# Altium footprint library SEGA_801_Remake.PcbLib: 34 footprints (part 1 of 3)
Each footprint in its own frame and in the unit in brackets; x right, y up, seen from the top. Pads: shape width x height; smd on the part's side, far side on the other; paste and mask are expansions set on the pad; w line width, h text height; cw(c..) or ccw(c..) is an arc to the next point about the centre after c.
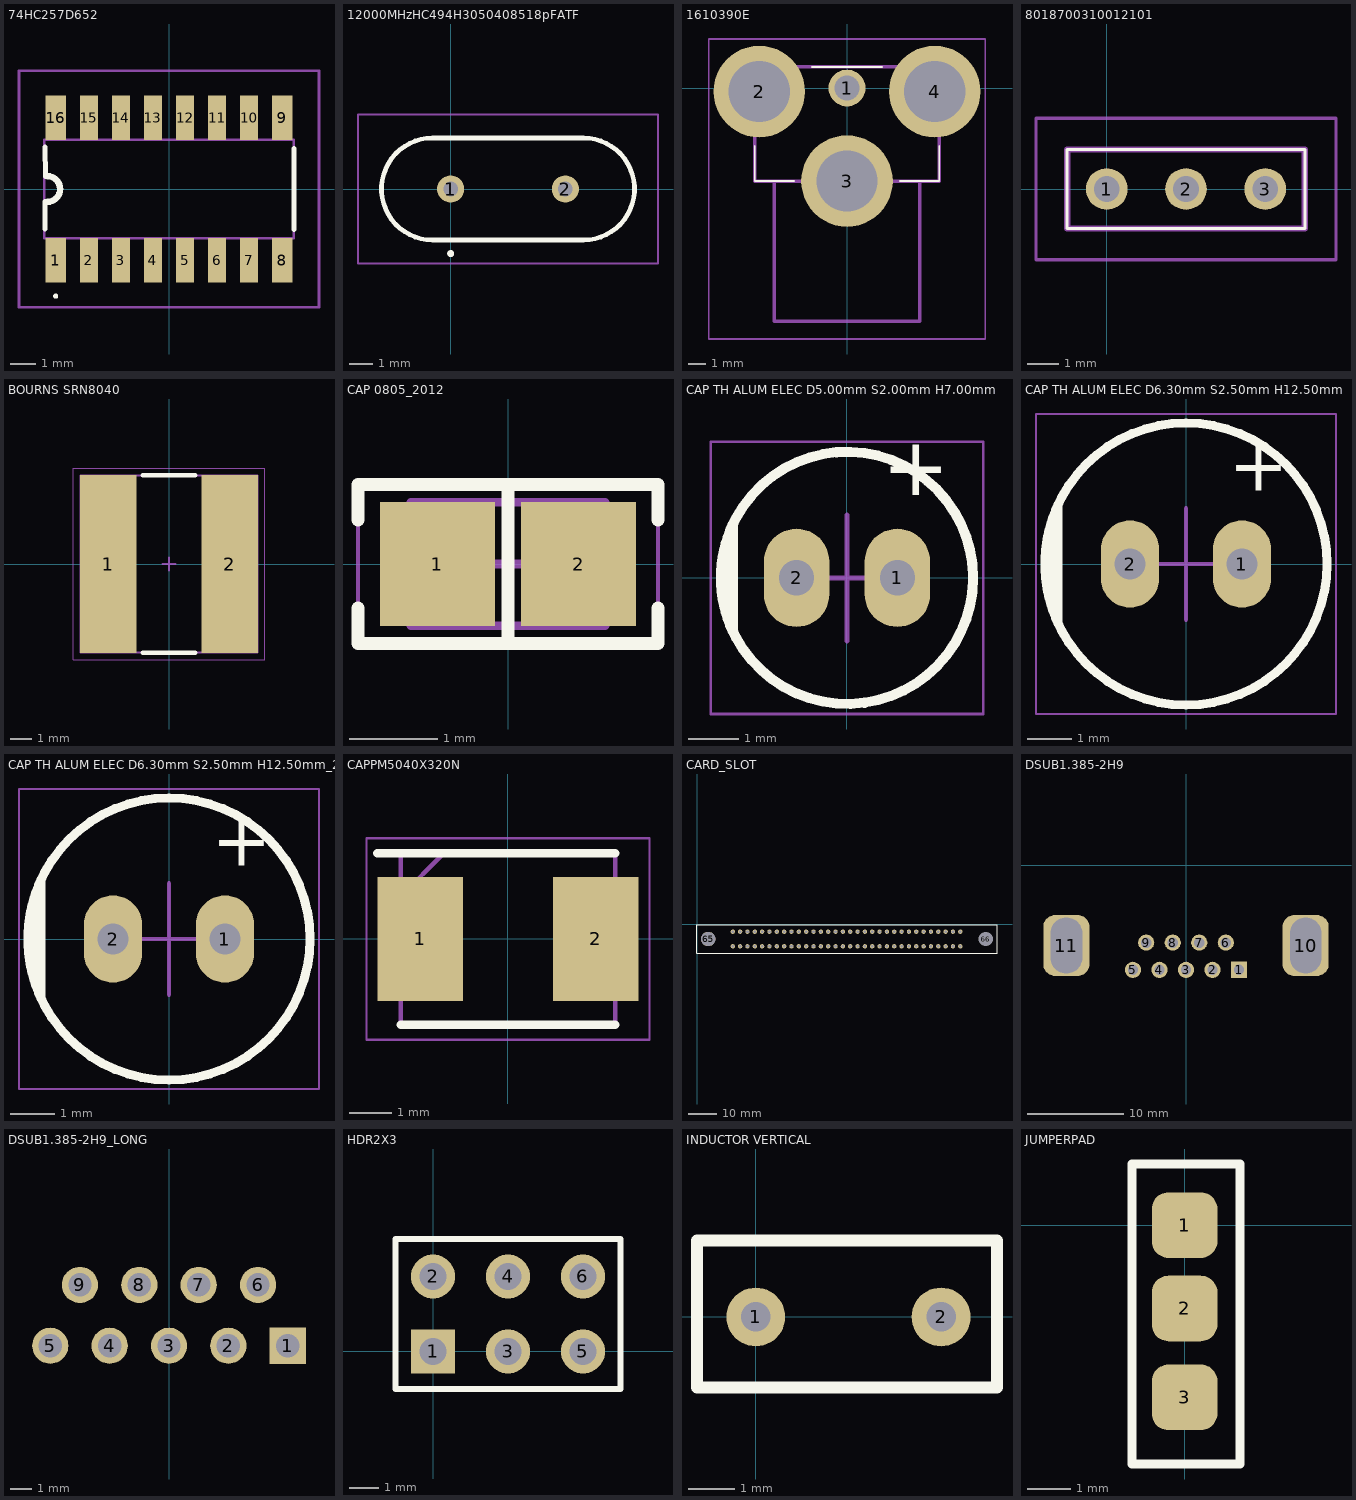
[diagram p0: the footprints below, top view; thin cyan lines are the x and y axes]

## 74HC257D652 [mm]
pads (16):
  rect 0.8x1.75 smd: 1(-4.495,-2.825) 8(4.495,-2.825) 9(4.495,2.825) 16(-4.495,2.825)
  rect 0.7x1.75 smd: 2(-3.175,-2.825) 3(-1.905,-2.825) 4(-0.635,-2.825) 5(0.635,-2.825) 6(1.905,-2.825) 7(3.175,-2.825) 10(3.175,2.825) 11(1.905,2.825) 12(0.635,2.825) 13(-0.635,2.825) 14(-1.905,2.825) 15(-3.175,2.825)
Top Overlay:
  lines w0.1: -4.495,-4.3 ccw(c-4.495,-4.25) -4.495,-4.2 ccw(c-4.495,-4.25) -4.495,-4.3
  lines w0.2: -4.917,-1.583 -4.914,-0.491 ; -4.914,1.668 -4.905,0.498 ; 4.95,-1.6 4.95,1.6
  lines w0.254: -4.819,0.508 cw(c-4.826,0) -4.816,-0.508
Mechanical 13:
  lines w0.1: -4.95,-1.95 -4.95,1.95 4.95,1.95 4.95,-1.95 -4.95,-1.95
Mechanical 15:
  lines w0.1: -5.95,-4.7 -5.95,4.7 5.95,4.7 5.95,-4.7 -5.95,-4.7
3D body "74HC257D,652.stp": height 1.56, standoff 0, extent -4.948,-3 4.952,3

## 12000MHzHC494H3050408518pFATF [mm]
pads (2):
  round 1.155 hole 0.63: 1(0,0) 2(4.88,0)
Top Overlay:
  lines w0.2: 0,-2.8 ccw(c0,-2.75) 0,-2.7 ; 0,-2.8 cw(c0,-2.75) 0,-2.7 ; 0,-2.8 ccw(c0,-2.75) 0,-2.7 ; -0.775,-2.17 cw(c-0.775,0) -0.775,2.17 5.655,2.17 cw(c5.655,0) 5.655,-2.17 -0.775,-2.17
Mechanical 13:
  lines w0.1: -0.775,-2.17 cw(c-0.775,0) -0.775,2.17 5.655,2.17 cw(c5.655,0) 5.655,-2.17 -0.775,-2.17
Mechanical 15:
  lines w0.1: -3.945,-3.17 8.825,-3.17 8.825,3.17 -3.945,3.17 -3.945,-3.17
3D body "12.000MHz_HC49_4H_30_50_-40+85_18pF_ATF.stp": height 3.5, standoff -13.2, extent -2.945,-2.17 7.825,2.17

## 1610390E [mm]
pads (4):
  round 2.1 hole 1.4: 1(0,0)
  round 5.218 hole 3.478: 2(-5,-0.2) 3(0,-5.3) 4(5,-0.2)
Top Overlay:
  lines w0.1: -5.25,-3.3 -5.25,-5.3 -3,-5.3 ; -2,1.2 2,1.2 ; 3,-5.3 5.25,-5.3 5.25,-3.3
Mechanical 13:
  lines w0.2: -4.15,-5.3 -4.15,-13.3 4.15,-13.3 4.15,-5.3 ; -5.25,-5.3 -5.25,1.2 5.25,1.2 5.25,-5.3 -5.25,-5.3
Mechanical 15:
  lines w0.1: -7.874,-14.3 7.874,-14.3 7.874,2.794 -7.874,2.794 -7.874,-14.3

## 8018700310012101 [mm]
pads (3):
  round 1.333 hole 0.82: 1(0,0) 2(2.54,0) 3(5.08,0)
Top Overlay:
  lines w0.1: -1.27,-1.27 -1.27,1.27 6.35,1.27 6.35,-1.27 -1.27,-1.27
Mechanical 13:
  lines w0.2: -1.27,-1.27 -1.27,1.27 6.35,1.27 6.35,-1.27 -1.27,-1.27
Mechanical 15:
  lines w0.1: -2.27,-2.27 -2.27,2.27 7.35,2.27 7.35,-2.27 -2.27,-2.27
3D body "801-87-003-10-012101.stp": height 4.3, standoff -5, extent -1.27,-1.27 6.35,1.27

## BOURNS SRN8040 [mm] "Power Inductor, 2-Leads, Bourns, SRN8040-220M"
height 4
pads (2):
  rect 2.6x8.2 smd: 1(-2.8,0) 2(2.8,0)
Top Overlay:
  lines w0.2: -1.2,-4.075 1.2,-4.075 ; -1.2,4.075 1.2,4.075
Mechanical 13:
  lines w0.1: -4.075,-4.075 -4.075,4.075 4.075,4.075 4.075,-4.075 -4.075,-4.075
Mechanical 15:
  lines w0.05: -4.4,-4.4 4.4,-4.4 4.4,4.4 -4.4,4.4 -4.4,-4.4
  lines w0.1: -0.3,0 0.3,0 ; 0,-0.3 0,0.3
3D body "Bourns - SRN8040.step": height 4, standoff 0, extent -4.075,-4.075 4.075,4.075

## CAP 0805_2012 [mm] "Chip Capacitor, 2-Leads, Body 2.00x1.20mm, IPC Medium Density"
height 1.15
pads (2):
  rect 1.3x1.4 smd: 1(-0.8,0) 2(0.8,0)
Top Overlay:
  lines w0.15: -1.7,-0.5 -1.7,-0.9 1.7,-0.9 1.7,-0.5 ; -1.7,0.5 -1.7,0.9 1.7,0.9 1.7,0.5 ; 0,-0.9 0,0.9
Mechanical 13:
  lines w0.1: -1.1,-0.7 1.1,-0.7 1.1,0.7 -1.1,0.7 -1.1,-0.7
Mechanical 15:
  lines w0.05: -1.7,-0.95 1.7,-0.95 1.7,0.95 -1.7,0.95 -1.7,-0.95
  lines w0.1: -0.5,0 0.5,0 ; 0,-0.5 0,0.5
3D body "0805 cap.STEP": height 1.26, standoff -0.02, extent -1,-0.637 1,0.637

## CAP TH ALUM ELEC D5.00mm S2.00mm H7.00mm [mm] "5mm Diameter 2mm Lead Spacing Aluminum Electrolytic Capacitors Radial, Can"
height 7
pads (2):
  oval 1.3x1.95 hole 0.7: 1(1,0) 2(-1,0)
Top Overlay:
  circle w0.2: c0,0 r2.5
  region: -2.266,-1.057 -2.323,-0.933 -2.411,-0.674 -2.47,-0.408 -2.5,-0.136 -2.5,0.136 -2.47,0.408 -2.411,0.674 -2.323,0.933 -2.266,1.057
  lines w0.2: -2.266,-1.057 cw(c0,0) -2.266,1.057 -2.266,-1.057
  text "+" at 0.7,1.25 h2
Mechanical 13:
  circle w0.1: c0,0 r2.5
  lines w0.1: -2.266,-1.057 -2.266,1.057
Mechanical 15:
  lines w0.05: -2.7,-2.7 2.7,-2.7 2.7,2.7 -2.7,2.7 -2.7,-2.7
  lines w0.1: -1.25,0 0,0 ; 0,-1.25 0,0 ; 0,1.25 0,0 ; 1.25,0 0,0
3D body "Cap TH D5.00mm H7.00mm L2.00mm.step": height 7, standoff -2.5, extent -2.509,-2.497 2.5,2.497

## CAP TH ALUM ELEC D6.30mm S2.50mm H12.50mm [mm] "6.3mm Diameter 2.5mm Lead Spacing Aluminum Electrolytic Capacitors Radial, Can"
height 12.5
pads (2):
  oval 1.3x1.95 hole 0.7: 1(1.25,0) 2(-1.25,0)
Top Overlay:
  circle w0.2: c0,0 r3.15
  region: -2.855,-1.331 -2.928,-1.175 -3.038,-0.85 -3.113,-0.514 -3.15,-0.172 -3.15,0.172 -3.113,0.514 -3.038,0.85 -2.928,1.175 -2.855,1.331
  lines w0.2: -2.855,-1.331 cw(c0,0) -2.855,1.331 -2.855,-1.331
  text "+" at 0.95,1.25 h2
Mechanical 13:
  circle w0.1: c0,0 r3.15
  lines w0.1: -2.855,-1.331 -2.855,1.331
Mechanical 15:
  lines w0.05: -3.35,-3.35 3.35,-3.35 3.35,3.35 -3.35,3.35 -3.35,-3.35
  lines w0.1: -1.25,0 0,0 ; 0,-1.25 0,0 ; 0,1.25 0,0 ; 1.25,0 0,0
3D body "Cap TH D6.30mm H12.50mm L2.50mm.step": height 12.5, standoff -2.5, extent -3.158,-3.15 3.15,3.15

## CAP TH ALUM ELEC D6.30mm S2.50mm H12.50mm_2 [mm]
pads (2):
  oval 1.3x1.95 hole 0.7: 1(1.25,0) 2(-1.25,0)
Top Overlay:
  circle w0.2: c0,0 r3.15
  region: -2.855,-1.331 -2.928,-1.175 -3.038,-0.85 -3.113,-0.514 -3.15,-0.172 -3.15,0.172 -3.113,0.514 -3.038,0.85 -2.928,1.175 -2.855,1.331
  lines w0.2: -2.855,-1.331 cw(c0,0) -2.855,1.331 -2.855,-1.331
  text "+" at 0.95,1.25 h2
Mechanical 13:
  circle w0.1: c0,0 r3.15
  lines w0.1: -2.855,-1.331 -2.855,1.331
Mechanical 15:
  lines w0.05: -3.35,-3.35 -3.35,3.35 3.35,3.35 3.35,-3.35 -3.35,-3.35
  lines w0.1: -1.25,0 0,0 ; 0,-1.25 0,0 ; 0,1.25 0,0 ; 1.25,0 0,0
3D body "Cap TH D6.30mm H12.50mm L2.50mm.step": height 12.5, standoff -2.5, extent -3.158,-3.15 3.15,3.15

## CAPPM5040X320N [mm]
pads (2):
  rect 2x2.9 smd: 1(-2.05,0) 2(2.05,0)
Top Overlay:
  lines w0.2: -3.05,2 2.5,2 ; -2.5,-2 2.5,-2
Mechanical 13:
  lines w0.1: -2.5,1 -1.5,2 ; -2.5,-2 2.5,-2 2.5,2 -2.5,2 -2.5,-2
Mechanical 15:
  lines w0.05: -3.3,-2.35 3.3,-2.35 3.3,2.35 -3.3,2.35 -3.3,-2.35
3D body "TZB4P400AB10R00.stp": height 3.2, standoff 0, extent -2.5,-2 2.5,2

## CARD_SLOT [mm]
pads (66):
  round 1.5 hole 0.9: 1(12.351,-7.652) 2(14.891,-7.652) 3(17.431,-7.652) 4(19.971,-7.652) 5(22.511,-7.652) 6(25.051,-7.652) 7(27.591,-7.652) 8(30.131,-7.652) 9(32.671,-7.652) 10(35.211,-7.652) 11(37.751,-7.652) 12(40.291,-7.652) 13(42.831,-7.652) 14(45.371,-7.652) 15(47.911,-7.652) 16(50.451,-7.652) 17(52.991,-7.652) 18(55.531,-7.652) 19(58.071,-7.652) 20(60.611,-7.652) 21(63.151,-7.652) 22(65.691,-7.652) 23(68.231,-7.652) 24(70.771,-7.652) 25(73.311,-7.652) 26(75.851,-7.652) 27(78.391,-7.652) 28(80.931,-7.652) 29(83.471,-7.652) 30(86.011,-7.652) 31(88.551,-7.652) 32(91.091,-7.652) 33(91.091,-2.572) 34(88.551,-2.572) 35(86.011,-2.572) 36(83.471,-2.572) 37(80.931,-2.572) 38(78.391,-2.572) 39(75.851,-2.572) 40(73.311,-2.572) 41(70.771,-2.572) 42(68.231,-2.572) 43(65.691,-2.572) 44(63.151,-2.572) 45(60.611,-2.572) 46(58.071,-2.572) 47(55.531,-2.572) 48(52.991,-2.572) 49(50.451,-2.572) 50(47.911,-2.572) 51(45.371,-2.572) 52(42.831,-2.572) 53(40.291,-2.572) 54(37.751,-2.572) 55(35.211,-2.572) 56(32.671,-2.572) 57(30.131,-2.572) 58(27.591,-2.572) 59(25.051,-2.572) 60(22.511,-2.572) 61(19.971,-2.572) 62(17.431,-2.572) 63(14.891,-2.572) 64(12.351,-2.572)
  round 5 hole 5: 65(3.805,-5.112)
  round 4 hole 5: 66(99.835,-5.112)
Top Overlay:
  lines w0.254: -0.032,-10.112 103.791,-10.112 103.791,-0.112 -0.032,-0.112 -0.032,-10.112

## DSUB1.385-2H9 [mm] "Connector; D Subminiature; 9 Position; Right Angle; Pitch 1.385 mm"
height 12.75
pads (11):
  rect 1.69x1.69 hole 1.09: 1(5.54,-10.92)
  round 1.69 hole 1.09: 2(2.77,-10.92) 3(0,-10.92) 4(-2.77,-10.92) 5(-5.54,-10.92) 6(4.155,-8.08) 7(1.385,-8.08) 8(-1.385,-8.08) 9(-4.155,-8.08)
  rrect50% 4.826x6.35 hole 3.26 slot 5.842 at 90 deg: 10(12.495,-8.382)
  rrect50% 4.826x6.35 hole 3.302 slot 5.842 at 90 deg: 11(-12.495,-8.382)
Bottom Overlay:
  lines w0.2: -7,-12.4 -7,-3 ; 7,-12.4 7,-3 ; -15.4,-12.4 15.4,-12.4 15.4,-3 -15.4,-3 -15.4,-12.4

## DSUB1.385-2H9_LONG [mm] "Connector; D Subminiature; 9 Position; Right Angle; Pitch 1.385 mm"
height 12.75
pads (9):
  rect 1.69x1.69 hole 1.09: 1(5.54,-10.92)
  round 1.69 hole 1.09: 2(2.77,-10.92) 3(0,-10.92) 4(-2.77,-10.92) 5(-5.54,-10.92) 6(4.155,-8.08) 7(1.385,-8.08) 8(-1.385,-8.08) 9(-4.155,-8.08)
Bottom Overlay:
  lines w0.2: -7,-12.4 7,-12.4 7,-6.477 -7,-6.477 -7,-12.4

## HDR2X3 [mm] "Connector; Header; 3x2 Position"
pads (6):
  rect 1.5x1.5 hole 0.9: 1(0,0)
  round 1.5 hole 0.9: 2(0,2.54) 3(2.54,0) 4(2.54,2.54) 5(5.08,0) 6(5.08,2.54)
Top Overlay:
  lines w0.2: 1.482,-1.27 6.35,-1.27 ; 6.35,-1.27 -1.27,-1.27 -1.27,3.81 6.35,3.81 6.35,-1.27

## INDUCTOR VERTICAL [mm]
pads (2):
  round 1.27 hole 0.635: 1(0,0) 2(4,0)
Top Overlay:
  lines w0.254: -1.27,-1.524 -1.27,1.651 5.207,1.651 5.207,-1.524 -1.27,-1.524

## JUMPERPAD [mm]
pads (3):
  rrect50% 1.5x1.5 smd: 1(0,0) 2(0,-1.905) 3(0,-3.937)
Top Overlay:
  lines w0.203: 1.206,-5.461 -1.206,-5.461 -1.206,1.397 1.206,1.397 ; 1.27,-5.461 1.27,1.397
